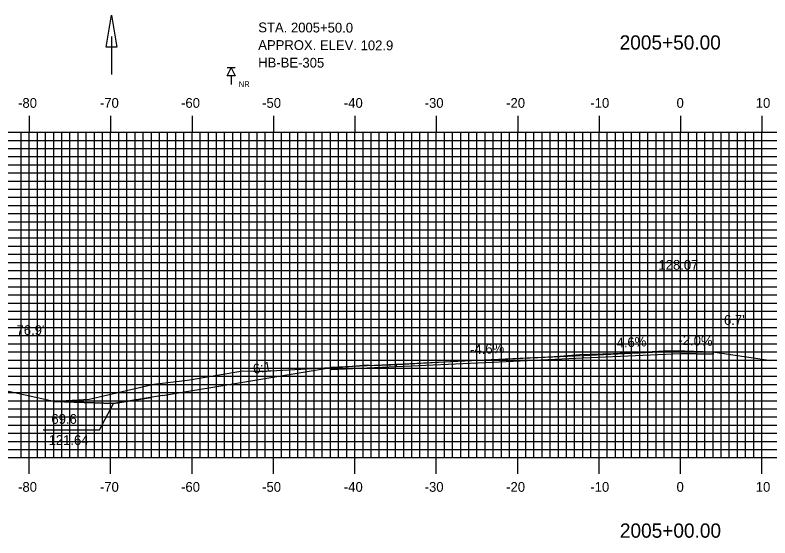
# Model space of a CAD drawing. Extents: x 851926 to 852269, y 366605 to 366825.
# Drawn here: x 852010.2 to 852103, y 366673.2 to 366737.5 of the extents above; entities that cross this region are included whole.
import ezdxf

# ---------------------------------------------------------------- set-up
doc = ezdxf.new("R2010")
doc.units = 0
for name, color, linetype in [('ANNOTATION', 7, 'Continuous'), ('BORING - NO REFUSAL', 7, 'Continuous'), ('D_Drainage_Ditch_Line', 7, 'Continuous'), ('D_Roadway_Centerline', 7, 'Continuous'), ('D_Roadway_Centerline_Text', 7, 'Continuous'), ('D_Roadway_Edge_Shoulder', 7, 'Continuous'), ('D_Roadway_Edge_TW', 7, 'Continuous'), ('D_Roadway_SlopeLines', 7, 'Continuous'), ('D_Text_Standard', 7, 'Continuous'), ('H_V ANNOTATION', 7, 'Continuous'), ('M_Roadway_Centerline', 7, 'Continuous'), ('MAJOR', 7, 'Continuous'), ('MINOR', 7, 'Continuous'), ('S_Roadway_Centerline', 7, 'Continuous')]:
    doc.layers.add(name, color=color, linetype=linetype)

msp = doc.modelspace()

# ---------------------------------------------------------------- linework, layer by layer
at = {"layer": 'ANNOTATION'}
for points in [[(852028.321, 366690.695), (852022.321, 366689.695), (852015.06, 366689.974)], [(852013.662, 366686.485), (852020.591, 366686.485), (852022.321, 366689.695)]]:
    msp.add_lwpolyline(points, dxfattribs=at)
at = {"layer": 'BORING - NO REFUSAL'}
for p, q in [((852037.244, 366730.955), (852036.285, 366730.955)), ((852036.765, 366729.996), (852036.765, 366728.937))]:
    msp.add_line(p, q, dxfattribs=at)
msp.add_lwpolyline([(852036.765, 366730.955), (852037.244, 366729.996), (852036.285, 366729.996)], close=True, dxfattribs=at)
at = {"layer": 'D_Drainage_Ditch_Line'}
msp.add_line((852022.077, 366734.829), (852022.077, 366730.13), dxfattribs=at)
msp.add_lwpolyline([(852022.733, 366733.517), (852021.421, 366733.517), (852022.077, 366737.454)], close=True, dxfattribs=at)
at = {"layer": 'D_Roadway_Centerline'}
for p, q in [((852091.965, 366696.123), (852095.965, 366696.043)), ((852091.965, 366695.873), (852095.965, 366695.793)), ((852015.06, 366689.974), (852022.321, 366689.695)), ((852022.321, 366689.695), (852026.941, 366690.465))]:
    msp.add_line(p, q, dxfattribs=at)
at = {"layer": 'D_Roadway_Edge_Shoulder'}
for points in [[(852091.965, 366696.123), (852095.965, 366696.043), (852095.965, 366695.793), (852091.965, 366695.873)], [(852057.04, 366694.516), (852049.04, 366694.148), (852049.04, 366693.898), (852057.04, 366694.266)]]:
    msp.add_lwpolyline(points, close=True, dxfattribs=at)
at = {"layer": 'D_Roadway_Edge_TW'}
for points in [[(852079.965, 366695.571), (852067.964, 366695.019), (852067.964, 366694.769), (852079.965, 366695.321)], [(852091.965, 366696.123), (852079.965, 366695.571), (852079.965, 366695.321), (852091.965, 366695.873)], [(852067.964, 366695.019), (852057.04, 366694.516), (852057.04, 366694.266), (852067.964, 366694.769)]]:
    msp.add_lwpolyline(points, close=True, dxfattribs=at)
msp.add_lwpolyline([(852067.964, 366694.769), (852067.964, 366695.019)], dxfattribs=at)
at = {"layer": 'D_Roadway_SlopeLines'}
for p, q in [((852095.965, 366696.043), (852098.683, 366695.64)), ((852028.321, 366690.695), (852049.04, 366694.148))]:
    msp.add_line(p, q, dxfattribs=at)
at = {"layer": 'MAJOR'}
for p, q in [((852011.965, 366725.059), (852011.965, 366723.055)), ((852021.965, 366725.059), (852021.965, 366723.055)), ((852031.965, 366725.059), (852031.965, 366723.055)), ((852041.965, 366725.059), (852041.965, 366723.055)), ((852051.965, 366725.059), (852051.965, 366723.055)), ((852061.965, 366725.059), (852061.965, 366723.055)), ((852071.965, 366725.059), (852071.965, 366723.055)), ((852081.965, 366725.059), (852081.965, 366723.055)), ((852091.965, 366725.059), (852091.965, 366723.055)), ((852101.965, 366725.059), (852101.965, 366723.055)), ((851951.965, 366723.055), (852231.965, 366723.055)), ((851951.965, 366723.055), (852231.965, 366723.055)), ((852011.965, 366683.055), (852011.965, 366723.055)), ((852021.965, 366683.055), (852021.965, 366723.055)), ((852031.965, 366683.055), (852031.965, 366723.055)), ((852041.965, 366683.055), (852041.965, 366723.055)), ((852051.965, 366683.055), (852051.965, 366723.055)), ((852061.965, 366683.055), (852061.965, 366723.055)), ((852071.965, 366683.055), (852071.965, 366723.055)), ((852081.965, 366683.055), (852081.965, 366723.055)), ((852091.965, 366683.055), (852091.965, 366723.055)), ((852101.965, 366683.055), (852101.965, 366723.055)), ((851951.965, 366718.055), (852231.965, 366718.055)), ((851951.965, 366713.055), (852231.965, 366713.055)), ((851951.965, 366708.055), (852231.965, 366708.055)), ((851951.965, 366703.055), (852231.965, 366703.055)), ((851951.965, 366698.055), (852231.965, 366698.055)), ((851951.965, 366693.055), (852231.965, 366693.055)), ((851951.965, 366688.055), (852231.965, 366688.055)), ((851951.965, 366683.055), (852231.965, 366683.055)), ((851951.965, 366683.055), (852231.965, 366683.055)), ((852011.965, 366681.051), (852011.965, 366683.055)), ((852021.965, 366681.051), (852021.965, 366683.055)), ((852031.965, 366681.051), (852031.965, 366683.055)), ((852041.965, 366681.051), (852041.965, 366683.055)), ((852051.965, 366681.051), (852051.965, 366683.055)), ((852061.965, 366681.051), (852061.965, 366683.055)), ((852071.965, 366681.051), (852071.965, 366683.055)), ((852081.965, 366681.051), (852081.965, 366683.055)), ((852091.965, 366681.051), (852091.965, 366683.055)), ((852101.965, 366681.051), (852101.965, 366683.055))]:
    msp.add_line(p, q, dxfattribs=at)
at = {"layer": 'MINOR'}
for p, q in [((852010.965, 366683.055), (852010.965, 366723.055)), ((852012.965, 366683.055), (852012.965, 366723.055)), ((852013.965, 366683.055), (852013.965, 366723.055)), ((852014.965, 366683.055), (852014.965, 366723.055)), ((852015.965, 366683.055), (852015.965, 366723.055)), ((852016.965, 366683.055), (852016.965, 366723.055)), ((852017.965, 366683.055), (852017.965, 366723.055)), ((852018.965, 366683.055), (852018.965, 366723.055)), ((852019.965, 366683.055), (852019.965, 366723.055)), ((852020.965, 366683.055), (852020.965, 366723.055)), ((852022.965, 366683.055), (852022.965, 366723.055)), ((852023.965, 366683.055), (852023.965, 366723.055)), ((852024.965, 366683.055), (852024.965, 366723.055)), ((852025.965, 366683.055), (852025.965, 366723.055)), ((852026.965, 366683.055), (852026.965, 366723.055)), ((852027.965, 366683.055), (852027.965, 366723.055)), ((852028.965, 366683.055), (852028.965, 366723.055)), ((852029.965, 366683.055), (852029.965, 366723.055)), ((852030.965, 366683.055), (852030.965, 366723.055)), ((852032.965, 366683.055), (852032.965, 366723.055)), ((852033.965, 366683.055), (852033.965, 366723.055)), ((852034.965, 366683.055), (852034.965, 366723.055)), ((852035.965, 366683.055), (852035.965, 366723.055)), ((852036.965, 366683.055), (852036.965, 366723.055)), ((852037.965, 366683.055), (852037.965, 366723.055)), ((852038.965, 366683.055), (852038.965, 366723.055)), ((852039.965, 366683.055), (852039.965, 366723.055)), ((852040.965, 366683.055), (852040.965, 366723.055)), ((852042.965, 366683.055), (852042.965, 366723.055)), ((852043.965, 366683.055), (852043.965, 366723.055)), ((852044.965, 366683.055), (852044.965, 366723.055)), ((852045.965, 366683.055), (852045.965, 366723.055)), ((852046.965, 366683.055), (852046.965, 366723.055)), ((852047.965, 366683.055), (852047.965, 366723.055)), ((852048.965, 366683.055), (852048.965, 366723.055)), ((852049.965, 366683.055), (852049.965, 366723.055)), ((852050.965, 366683.055), (852050.965, 366723.055)), ((852052.965, 366683.055), (852052.965, 366723.055)), ((852053.965, 366683.055), (852053.965, 366723.055)), ((852054.965, 366683.055), (852054.965, 366723.055)), ((852055.965, 366683.055), (852055.965, 366723.055)), ((852056.965, 366683.055), (852056.965, 366723.055)), ((852057.965, 366683.055), (852057.965, 366723.055)), ((852058.965, 366683.055), (852058.965, 366723.055)), ((852059.965, 366683.055), (852059.965, 366723.055)), ((852060.965, 366683.055), (852060.965, 366723.055)), ((852062.965, 366683.055), (852062.965, 366723.055)), ((852063.965, 366683.055), (852063.965, 366723.055)), ((852064.965, 366683.055), (852064.965, 366723.055)), ((852065.965, 366683.055), (852065.965, 366723.055)), ((852066.965, 366683.055), (852066.965, 366723.055)), ((852067.965, 366683.055), (852067.965, 366723.055)), ((852068.965, 366683.055), (852068.965, 366723.055)), ((852069.965, 366683.055), (852069.965, 366723.055)), ((852070.965, 366683.055), (852070.965, 366723.055)), ((852072.965, 366683.055), (852072.965, 366723.055)), ((852073.965, 366683.055), (852073.965, 366723.055)), ((852074.965, 366683.055), (852074.965, 366723.055)), ((852075.965, 366683.055), (852075.965, 366723.055)), ((852076.965, 366683.055), (852076.965, 366723.055)), ((852077.965, 366683.055), (852077.965, 366723.055)), ((852078.965, 366683.055), (852078.965, 366723.055)), ((852079.965, 366683.055), (852079.965, 366723.055)), ((852080.965, 366683.055), (852080.965, 366723.055)), ((852082.965, 366683.055), (852082.965, 366723.055)), ((852083.965, 366683.055), (852083.965, 366723.055)), ((852084.965, 366683.055), (852084.965, 366723.055)), ((852085.965, 366683.055), (852085.965, 366723.055)), ((852086.965, 366683.055), (852086.965, 366723.055)), ((852087.965, 366683.055), (852087.965, 366723.055)), ((852088.965, 366683.055), (852088.965, 366723.055)), ((852089.965, 366683.055), (852089.965, 366723.055)), ((852090.965, 366683.055), (852090.965, 366723.055)), ((852092.965, 366683.055), (852092.965, 366723.055)), ((852093.965, 366683.055), (852093.965, 366723.055)), ((852094.965, 366683.055), (852094.965, 366723.055)), ((852095.965, 366683.055), (852095.965, 366723.055)), ((852096.965, 366683.055), (852096.965, 366723.055)), ((852097.965, 366683.055), (852097.965, 366723.055)), ((852098.965, 366683.055), (852098.965, 366723.055)), ((852099.965, 366683.055), (852099.965, 366723.055)), ((852100.965, 366683.055), (852100.965, 366723.055)), ((851951.965, 366722.055), (852231.965, 366722.055)), ((851951.965, 366721.055), (852231.965, 366721.055)), ((851951.965, 366720.055), (852231.965, 366720.055)), ((851951.965, 366719.055), (852231.965, 366719.055)), ((851951.965, 366717.055), (852231.965, 366717.055)), ((851951.965, 366716.055), (852231.965, 366716.055)), ((851951.965, 366715.055), (852231.965, 366715.055)), ((851951.965, 366714.055), (852231.965, 366714.055)), ((851951.965, 366712.055), (852231.965, 366712.055)), ((851951.965, 366711.055), (852231.965, 366711.055)), ((851951.965, 366710.055), (852231.965, 366710.055)), ((851951.965, 366709.055), (852231.965, 366709.055)), ((851951.965, 366707.055), (852231.965, 366707.055)), ((851951.965, 366706.055), (852231.965, 366706.055)), ((851951.965, 366705.055), (852231.965, 366705.055)), ((851951.965, 366704.055), (852231.965, 366704.055)), ((851951.965, 366702.055), (852231.965, 366702.055)), ((851951.965, 366701.055), (852231.965, 366701.055)), ((851951.965, 366700.055), (852231.965, 366700.055)), ((851951.965, 366699.055), (852231.965, 366699.055)), ((851951.965, 366697.055), (852231.965, 366697.055)), ((851951.965, 366696.055), (852231.965, 366696.055)), ((851951.965, 366695.055), (852231.965, 366695.055)), ((851951.965, 366694.055), (852231.965, 366694.055)), ((851951.965, 366692.055), (852231.965, 366692.055)), ((851951.965, 366691.055), (852231.965, 366691.055)), ((851951.965, 366690.055), (852231.965, 366690.055)), ((851951.965, 366689.055), (852231.965, 366689.055)), ((851951.965, 366687.055), (852231.965, 366687.055)), ((851951.965, 366686.055), (852231.965, 366686.055)), ((851951.965, 366685.055), (852231.965, 366685.055)), ((851951.965, 366684.055), (852231.965, 366684.055))]:
    msp.add_line(p, q, dxfattribs=at)
at = {"layer": 'S_Roadway_Centerline'}
msp.add_lwpolyline([(852005.123, 366692.174), (852014.605, 366690.077), (852015.042, 366689.976), (852015.06, 366689.974), (852015.128, 366689.986), (852019.34, 366690.229), (852027.27, 366692.104), (852031.412, 366692.595), (852038.194, 366693.733), (852039.566, 366693.685), (852040.907, 366693.693), (852051.188, 366694.267), (852053.53, 366694.454), (852054.069, 366694.371), (852056.385, 366694.463), (852065.187, 366694.939), (852074.891, 366695.395), (852076.468, 366695.468), (852076.647, 366695.486), (852079.607, 366695.734), (852082.416, 366695.817), (852083.737, 366695.835), (852090.064, 366696.166), (852092.496, 366696.178), (852095.882, 366696.053), (852101.483, 366695.227), (852103.079, 366695.015)], dxfattribs=at)

# ---------------------------------------------------------------- texts
at = {"layer": 'ANNOTATION'}
for s, rotation, p in [('-4.6%', 2.6338, (852083.607, 366696.541)), ('-2.0%', 357.70948, (852091.691, 366696.936)), ('-4.6%', 2.63485, (852066.143, 366695.737)), ('6:1', 9.46171, (852039.566, 366693.333)), ("69.6' ", 360, (852014.688, 366687.211)), ('121.64', 360, (852014.34, 366684.611))]:
    msp.add_text(s, height=1.2, rotation=rotation, dxfattribs=at).set_placement(p)
at = {"layer": 'BORING - NO REFUSAL'}
for s, p in [('STA. 2005+50.0', (852040.099, 366735.341)), ('APPROX. ELEV. 102.9', (852040.092, 366733.181)), ('HB-BE-305', (852040.085, 366731.021))]:
    msp.add_text(s, height=1.2, rotation=359.81416, dxfattribs=at).set_placement(p)
msp.add_text('NR', height=0.6998, dxfattribs=at).set_placement((852037.697, 366728.616))
at = {"layer": 'D_Roadway_Centerline_Text'}
msp.add_text('128.07', height=1.2, dxfattribs=at).set_placement((852089.257, 366706.153))
at = {"layer": 'D_Text_Standard'}
for s, p in [("6.7'", (852097.309, 366699.376)), ("76.9'", (852010.406, 366698.133))]:
    msp.add_text(s, height=1.2, dxfattribs=at).set_placement(p)
at = {"layer": 'H_V ANNOTATION'}
for s, height, p in [('2005+50.00', 1.75, (852084.489, 366733.211)), ('-80', 1.2, (852010.594, 366726.055)), ('-70', 1.2, (852020.648, 366726.055)), ('-60', 1.2, (852030.616, 366726.055)), ('-50', 1.2, (852040.573, 366726.055)), ('-40', 1.2, (852050.616, 366726.055)), ('-30', 1.2, (852060.541, 366726.055)), ('-20', 1.2, (852070.552, 366726.055)), ('-10', 1.2, (852080.894, 366726.055)), ('0', 1.2, (852091.483, 366726.055)), ('10', 1.2, (852101.215, 366726.055)), ('-80', 1.2, (852010.594, 366678.855)), ('-70', 1.2, (852020.648, 366678.855)), ('-60', 1.2, (852030.616, 366678.855)), ('-50', 1.2, (852040.573, 366678.855)), ('-40', 1.2, (852050.616, 366678.855)), ('-30', 1.2, (852060.541, 366678.855)), ('-20', 1.2, (852070.552, 366678.855)), ('-10', 1.2, (852080.894, 366678.855)), ('0', 1.2, (852091.483, 366678.855)), ('10', 1.2, (852101.215, 366678.855)), ('2005+00.00', 1.75, (852084.52, 366673.211))]:
    msp.add_text(s, height=height, dxfattribs=at).set_placement(p)
at = {"layer": 'M_Roadway_Centerline'}
for s, p in [('C', (852079.602, 366695.734)), ('L', (852079.607, 366695.727)), ('C', (852053.525, 366694.454)), ('L', (852053.53, 366694.446))]:
    msp.add_text(s, height=0.0146, dxfattribs=at).set_placement(p)

doc.saveas('drawing.dxf')
